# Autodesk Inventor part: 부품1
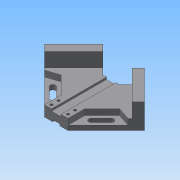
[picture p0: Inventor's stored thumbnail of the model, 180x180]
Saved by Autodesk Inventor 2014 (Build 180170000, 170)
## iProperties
Created: 2019-04
Part Number: 부품1
Material: 일반
Document SubType Name: Modeling
Designer: net
Density: 1 g/cm^3
Appearance: 기본값
Author: net
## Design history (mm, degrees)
sketch "스케치2"
  geometry: L1 (0, 84.853)-(-84.853, 0); L2 (-84.853, 0)-(0, -84.853); L3 (0, -84.853)-(84.853, 0); L4 (84.853, 0)-(0, 84.853); L5 (0, 84.853)-(0, -84.853); L6 (-84.853, 0)-(84.853, 0); 2 further points
  constraints: 12 end point, 3 midpoint, 2 parallel, 1 perpendicular, 1 vertical alignment
  dimensions: "d3" = 120 distance between parallel lines of L3 L1; "d4" = 120 distance between parallel lines of L2 L4
extrude "돌출1" new body sketch "스케치2" distance "d5" = 42; taper "d6" = 0 deg
sketch "스케치4"
  geometry: L1 (-84.853, 0)-(0, -84.853) reference; L2 (0, -84.853)-(84.853, 0) reference; L3 (-20, -64.853)-(20, -64.853); 1 further point
  constraints: 2 end point, 2 point on line, 1 horizontal
  dimensions: "d9" = 20 distance from line of L1.end L3
extrude "돌출2" cut sketch "스케치4" distance "d10" = 42; taper "d11" = 0 deg
sketch "스케치5"
  geometry: L1 (-20, -64.853)-(20, -64.853) reference; L2 (20, -64.853)-(84.853, 0) reference; L3 (84.853, 0)-(0, 84.853) reference; L4 (0, 84.853)-(-84.853, 0) reference; L5 (-84.853, 0)-(-20, -64.853) reference; L6 (74.246, -10.607)-(0, 63.64); L7 (-74.246, -10.607)-(0, 63.64); 1 further point
  constraints: 4 end point, 2 perpendicular, 2 point on line
  dimensions: "d12" = 15 distance between parallel lines of L3 L6; "d13" = 15 distance between parallel lines of L7 L4
extrude "돌출3" cut sketch "스케치5" distance "d14" = 24; taper "d15" = 0 deg
sketch "스케치6"
  geometry: L1 (84.853, 0)-(0, 84.853) reference; L2 (0, 84.853)-(-84.853, 0) reference; L3 (20, -64.853)-(-20, -64.853) reference; L4 (74.246, -10.607)-(20, -64.853) reference; L5 (0, 63.64)-(74.246, -10.607) reference; L6 (-74.246, -10.607)-(0, 63.64) reference; L7 (-20, -64.853)-(-74.246, -10.607) reference; L8 (-35.355, 49.497)-(-14.005, 28.147); L9 (-14.005, 28.147)-(14.005, 28.147); L10 (14.005, 28.147)-(35.355, 49.497); 1 further point
  constraints: 6 end point, 2 parallel, 2 point on line, 1 perpendicular
  dimensions: "d16" = 50 distance between parallel lines of L2 L10; "d17" = 50 distance between parallel lines of L8 L1; "d18" = 93 distance between parallel lines of L3 L9
extrude "돌출4" cut sketch "스케치6" distance "d19" = 50; taper "d20" = 0 deg
sketch "스케치7"
  geometry: L1 (14.005, 28.147)-(-14.005, 28.147) reference; L2 (20, -64.853)-(-20, -64.853) reference; L3 (-8, 28.147)-(-8, -64.853); L4 (8, 28.147)-(8, -64.853); 1 further point
  constraints: 4 end point, 4 point on line, 1 parallel, 1 perpendicular
  dimensions: "d21" = 16 distance between parallel lines of L3 L4; "d22" = 8 distance from line of point (0, 0) L3
extrude "돌출5" cut sketch "스케치7" distance "d23" = 3.5; taper "d24" = 0 deg
sketch "스케치8"
  geometry: L1 (-20, -64.853)-(20, -64.853) reference; L2 (14.005, 28.147)-(-14.005, 28.147) reference; L3 (-6, 28.147)-(-6, -64.853); L4 (6, 28.147)-(6, -64.853); 1 further point
  constraints: 4 end point, 4 point on line, 2 perpendicular
  dimensions: "d25" = 12 distance between parallel lines of L4 L3; "d26" = 6 distance from line of point (0, 0) L3
extrude "돌출6" cut sketch "스케치8" distance "d27" = 3; taper "d28" = 0 deg
sketch "스케치11"
  geometry: L1 (6, -64.853)-(-6, -64.853) reference; C1 r 4 at (-14, -58.853); C2 r 4 at (-14, -46.853); 1 further point
  constraints: 2 centre point, 1 vertical alignment
  dimensions: "d39" = 6 distance from line of L1 C1.centre; "d40" = 12 distance of C2.centre C1.centre; "d41" = 14 horizontal distance of point (0, 0) C1.centre; "d42" = 8 diameter of C1; "d43" = 8 diameter of C2
extrude "돌출8" cut sketch "스케치11" distance "d44" = 10; taper "d45" = 0 deg
sketch "스케치12"
  geometry: L1 (8, -64.853)-(-8, -64.853) reference; C1 r 2.25 at (14, -46.853); C2 r 2.25 at (14, -58.853); 1 further point
  constraints: 2 centre point, 1 vertical alignment
  dimensions: "d46" = 14 horizontal distance of point (0, 0) C1.centre; "d47" = 12 distance of C2.centre C1.centre; "d48" = 4.5 diameter of C1; "d49" = 4.5 diameter of C2; "d50" = 6 distance from line of L1 C2.centre
extrude "돌출9" cut sketch "스케치12" distance "d51" = 20; taper "d52" = 0 deg
sketch "스케치14"
  geometry: L1 (-35.355, 49.497)-(-84.853, 0) reference; L2 (70.711, -14.142)-(49.497, -7.071); L3 (49.497, -7.071)-(20, -36.569); L4 (8, 28.147)-(8, -64.853) reference; L5 (20, -64.853)-(8, -64.853) reference; L6 (74.246, -10.607)-(20, -64.853) reference; L7 (24.749, 38.891)-(74.246, -10.607) reference; L8 (24.749, 38.891)-(14.005, 28.147) reference; L9 (14.005, 28.147)-(8, 28.147) reference; L10 (84.853, 0)-(35.355, 49.497) reference; L11 (35.355, 49.497)-(24.749, 38.891) reference; L12 (24.749, 38.891)-(74.246, -10.607) reference; L13 (74.246, -10.607)-(84.853, 0) reference; L14 (84.853, 0)-(35.355, 49.497) reference; L15 (74.246, -10.607)-(20, -64.853) reference; L16 (20, -36.569)-(20, -64.853); C1 r 2.25 at (14, -46.853) reference; C2 r 2.25 at (14, -58.853) reference; 1 further point
  constraints: 6 end point, 2 point on line, 1 parallel, 1 perpendicular
  dimensions: "d56" = 20 distance between parallel lines of L6 L3; "d57" = 20 distance from line of L2.start L10; "d58" = 30 distance from line of L10 L2.end; "d63" = 20 distance from line of point (0, 0) L16
extrude "돌출10" cut sketch "스케치14" distance "d64" = 10; taper "d65" = 0 deg
sketch "스케치15"
  geometry: L1 (70.711, -14.142)-(20, -64.853) reference; L2 (49.497, -21.213)-(32.527, -38.184); L3 (46.315, -18.031)-(29.345, -35.002); L4 (35.709, -41.366)-(52.679, -24.395); L5 (-49.497, -7.071)-(-20, -36.569) reference; L6 (-20, -36.569)-(-20, -64.853) reference; L7 (-8, -64.853)-(-20, -64.853) reference; L8 (-8, -64.853)-(-8, 28.147) reference; L9 (-8, 28.147)-(-14.005, 28.147) reference; L10 (-14.005, 28.147)-(-24.749, 38.891) reference; L11 (-74.246, -10.607)-(-24.749, 38.891) reference; L12 (-70.711, -14.142)-(-74.246, -10.607) reference; L13 (-70.711, -14.142)-(-49.497, -7.071) reference; L14 (-49.497, -7.071)-(-20, -36.569) reference; L15 (-20, -64.853)-(-70.711, -14.142) reference; L16 (84.853, 0)-(35.355, 49.497) reference; C1 r 2.25 at (-14, -46.853) reference; C2 r 2.25 at (-14, -58.853) reference; A1 r 4.5 centre (49.497, -21.213) between (52.679, -24.395) and (46.315, -18.031); A2 r 4.5 centre (32.527, -38.184) between (29.345, -35.002) and (35.709, -41.366); 2 further points
  constraints: 8 end point, 4 point on circle, 4 tangent, 2 centre point, 2 parallel, 1 midpoint
  dimensions: "d66" = 10 distance from line of L1 L2.start; "d67" = 40 distance from line of L16 L2.start; "d70" = 9 distance between parallel lines of L3 L4; "d72" = 24 distance of L2.start L2.end
extrude "돌출11" cut sketch "스케치15" distance "d73" = 50; taper "d74" = 0 deg
node "솔리드1"
mirror "대칭1"
mirror "대칭2"
mirror "대칭3"
mirror "대칭4"
node "투영된 루프1"
node "투영된 루프2"
node "투영된 루프3"
node "투영된 루프4"
